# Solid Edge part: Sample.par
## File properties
Author: edge
Template: jis part.par
Last saved by: edge
Revision: 4
Application: Solid Edge
Accuracy: 0.990
文書内容のタイプ: 0
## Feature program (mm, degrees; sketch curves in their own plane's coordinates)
sketch for "unnamed Protrusion 1" plane through (0, 0, 0) normal (0, -1, 0) x-axis (1, 0, 0)
  circle centre (0, 130) radius 32.5
extrude "unnamed Protrusion 1" add finite 40 symmetric
sketch for "unnamed Cutout 1" plane through (0, 0, 0) normal (0, -1, 0) x-axis (1, 0, 0)
  circle centre (0, 130) radius 18
extrude "unnamed Cutout 1" cut through
sketch for "ExtrudedProtrusion_2" plane through (0, 0, 0) normal (0, 0, 1) x-axis (1, 0, 0)
  line (-80, 90) -> (80, 90)
  line (80, 90) -> (80, 0)
  line (80, 0) -> (-80, 0)
  line (-80, 0) -> (-80, 90)
  dimension (linear) = 80
  dimension (linear) = 80
extrude "ExtrudedProtrusion_2" add finite 20 along -normal
sketch for "unnamed Protrusion 2" plane through (0, 0, 0) normal (0, 0, 1) x-axis (1, 0, 0)
  line (-25, 20) -> (25, 20)
  line (25, 20) -> (25, 0)
  line (25, 0) -> (-25, 0)
  line (-25, 0) -> (-25, 20)
  dimension (linear) = 25
  dimension (linear) = 25
extrude "unnamed Protrusion 2" add through along +normal
rib "Rib_1"  Thickness = 10 mm
sketch for "unnamed Cutout 2" #1 plane through (0, 0, 0) normal (0, 0, 1) x-axis (1, 0, 0)
  circle centre (-55, 60) radius 15
sketch for "unnamed Cutout 2" #2 plane through (0, 0, 0) normal (0, 0, 1) x-axis (1, 0, 0)
  circle centre (50, 60) radius 15
extrude "unnamed Cutout 2" cut through along -normal
fillet "Round_1" radius 20
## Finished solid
Body 1: solid body, 19 faces, 46 edges, 26 vertices.
  Faces by surface: plane 13, cylinder 6
  Edges by curve: line 33, circle 13
Bounding box of the edges (mm): 160.000 x 110.000 x 182.500, from (-80, -20, -20) to (80, 90, 162.5).
Cylindrical faces by radius (mm): R15 x2, R18 x1, R20 x2, R32.5 x1
Planar faces by outward normal: +x 3, +y 2, +z 1, -x 3, -y 2, -z 1, oblique 1
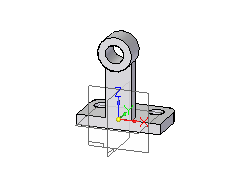
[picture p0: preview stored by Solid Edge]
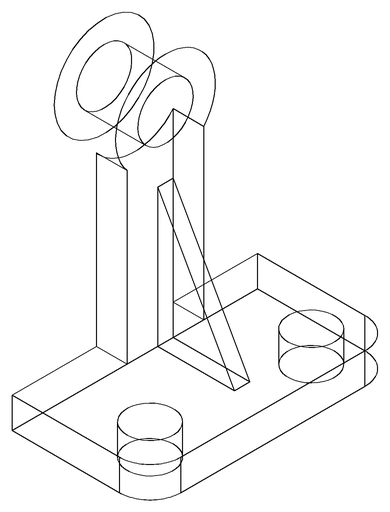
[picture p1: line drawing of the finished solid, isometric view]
